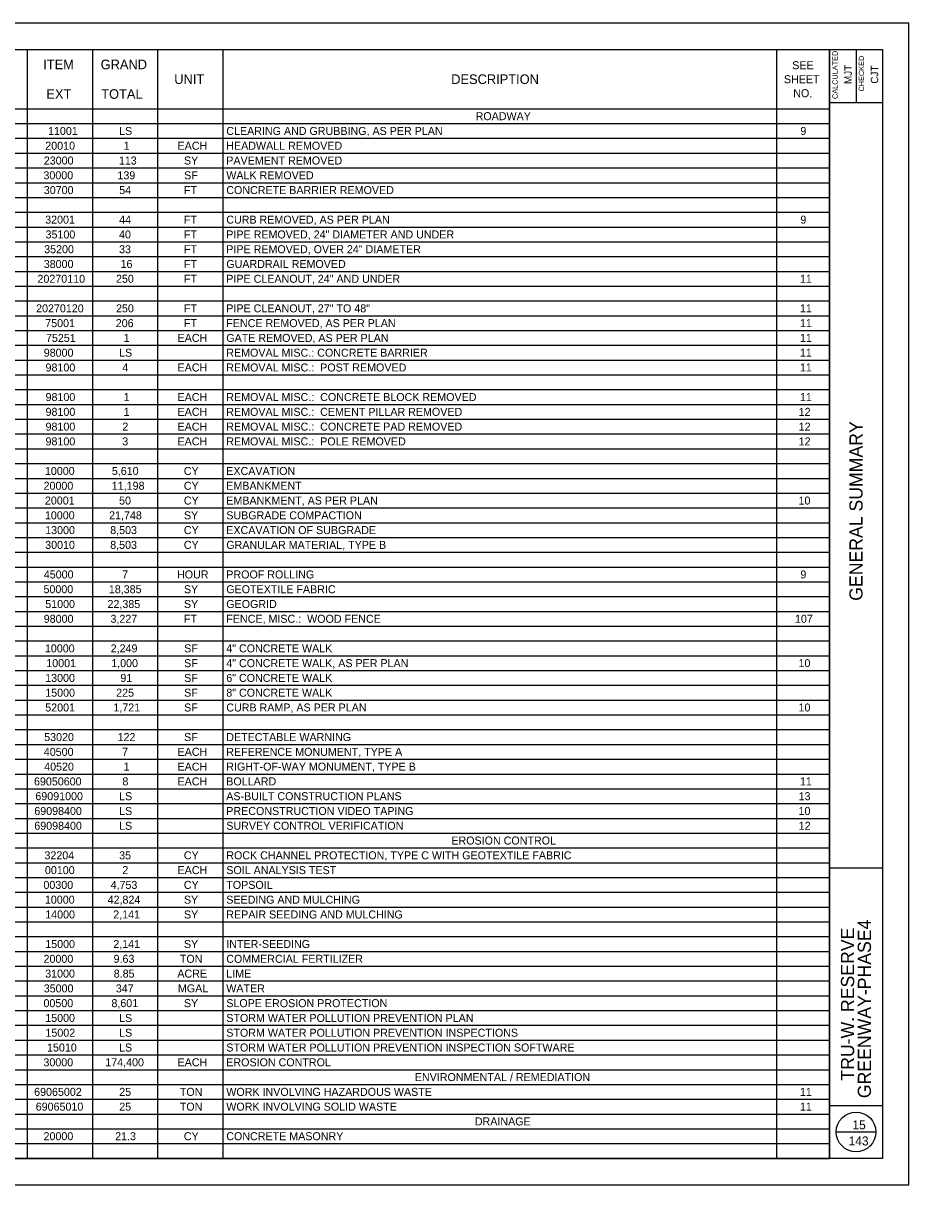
# Model space of a CAD drawing. Extents: x -16 to 102, y -13 to 9.
# Drawn here: x 0.85 to 17.63, y -12.91 to 9.09 of the extents above; entities that cross this region are included whole.
import ezdxf

# ---------------------------------------------------------------- set-up
doc = ezdxf.new("R2010")
doc.units = 0
for name, color, linetype in [('PV_P_EOP', 7, 'Continuous'), ('SH_Border', 7, 'Continuous'), ('SH_Cut_Line', 7, 'Continuous'), ('SH_Data', 7, 'Continuous'), ('TX_P_1', 7, 'Continuous')]:
    doc.layers.add(name, color=color, linetype=linetype)

msp = doc.modelspace()

# ---------------------------------------------------------------- linework, layer by layer
at = {"layer": 'SH_Border'}
for p, q in [((16.129, -12.407), (16.129, 8.593)), ((16.629, 8.593), (16.629, 7.593)), ((16.129, 7.593), (17.129, 7.593)), ((16.129, -6.907), (17.129, -6.907)), ((16.129, -11.407), (17.129, -11.407))]:
    msp.add_line(p, q, dxfattribs=at)
msp.add_lwpolyline([(-14.371, 8.593), (17.129, 8.593), (17.129, -12.407), (-14.371, -12.407)], close=True, dxfattribs=at)
at = {"layer": 'SH_Cut_Line'}
msp.add_lwpolyline([(-16.371, -12.907), (17.629, -12.907), (17.629, 9.093), (-16.371, 9.093)], close=True, dxfattribs=at)
at = {"layer": 'SH_Data'}
msp.add_line((16.254, -11.907), (17.004, -11.907), dxfattribs=at)
msp.add_circle((16.629, -11.907), 0.375, dxfattribs=at)
at = {"layer": 'TX_P_1'}
for p, q in [((-14.371, 8.593), (16.129, 8.593)), ((0.928, 8.593), (0.928, -12.407)), ((2.163, 8.593), (2.163, -12.407)), ((3.398, 8.593), (3.398, -12.407)), ((4.634, 8.593), (4.634, -12.407)), ((15.124, 8.593), (15.124, -12.407)), ((16.129, 8.593), (16.129, -12.407)), ((-14.371, 7.473), (16.129, 7.473)), ((-14.371, 7.193), (16.129, 7.193)), ((-14.371, 6.913), (16.129, 6.913)), ((-14.371, 6.633), (16.129, 6.633)), ((-14.371, 6.353), (16.129, 6.353)), ((-14.371, 6.073), (16.129, 6.073)), ((-14.371, 5.793), (16.129, 5.793)), ((-14.371, 5.513), (16.129, 5.513)), ((-14.371, 5.233), (16.129, 5.233)), ((-14.371, 4.953), (16.129, 4.953)), ((-14.371, 4.673), (16.129, 4.673)), ((-14.371, 4.393), (16.129, 4.393)), ((-14.371, 4.113), (16.129, 4.113)), ((-14.371, 3.833), (16.129, 3.833)), ((-14.371, 3.553), (16.129, 3.553)), ((-14.371, 3.273), (16.129, 3.273)), ((-14.371, 2.993), (16.129, 2.993)), ((-14.371, 2.713), (16.129, 2.713)), ((-14.371, 2.433), (16.129, 2.433)), ((-14.371, 2.153), (16.129, 2.153)), ((-14.371, 1.873), (16.129, 1.873)), ((-14.371, 1.593), (16.129, 1.593)), ((-14.371, 1.313), (16.129, 1.313)), ((-14.371, 1.033), (16.129, 1.033)), ((-14.371, 0.753), (16.129, 0.753)), ((-14.371, 0.473), (16.129, 0.473)), ((-14.371, 0.193), (16.129, 0.193)), ((-14.371, -0.087), (16.129, -0.087)), ((-14.371, -0.367), (16.129, -0.367)), ((-14.371, -0.647), (16.129, -0.647)), ((-14.371, -0.927), (16.129, -0.927)), ((-14.371, -1.207), (16.129, -1.207)), ((-14.371, -1.487), (16.129, -1.487)), ((-14.371, -1.767), (16.129, -1.767)), ((-14.371, -2.047), (16.129, -2.047)), ((-14.371, -2.327), (16.129, -2.327)), ((-14.371, -2.607), (16.129, -2.607)), ((-14.371, -2.887), (16.129, -2.887)), ((-14.371, -3.167), (16.129, -3.167)), ((-14.371, -3.447), (16.129, -3.447)), ((-14.371, -3.727), (16.129, -3.727)), ((-14.371, -4.007), (16.129, -4.007)), ((-14.371, -4.287), (16.129, -4.287)), ((-14.371, -4.567), (16.129, -4.567)), ((-14.371, -4.847), (16.129, -4.847)), ((-14.371, -5.127), (16.129, -5.127)), ((-14.371, -5.407), (16.129, -5.407)), ((-14.371, -5.687), (16.129, -5.687)), ((-14.371, -5.967), (16.129, -5.967)), ((-14.371, -6.247), (16.129, -6.247)), ((-14.371, -6.527), (16.129, -6.527)), ((-14.371, -6.807), (16.129, -6.807)), ((-14.371, -7.087), (16.129, -7.087)), ((-14.371, -7.367), (16.129, -7.367)), ((-14.371, -7.647), (16.129, -7.647)), ((-14.371, -7.927), (16.129, -7.927)), ((-14.371, -8.207), (16.129, -8.207)), ((-14.371, -8.487), (16.129, -8.487)), ((-14.371, -8.767), (16.129, -8.767)), ((-14.371, -9.047), (16.129, -9.047)), ((-14.371, -9.327), (16.129, -9.327)), ((-14.371, -9.607), (16.129, -9.607)), ((-14.371, -9.887), (16.129, -9.887)), ((-14.371, -10.167), (16.129, -10.167)), ((-14.371, -10.447), (16.129, -10.447)), ((-14.371, -10.727), (16.129, -10.727)), ((-14.371, -11.007), (16.129, -11.007)), ((-14.371, -11.287), (16.129, -11.287)), ((-14.371, -11.567), (16.129, -11.567)), ((-14.371, -11.847), (16.129, -11.847)), ((-14.371, -12.127), (16.129, -12.127)), ((-14.371, -12.407), (16.129, -12.407))]:
    msp.add_line(p, q, dxfattribs=at)

# ---------------------------------------------------------------- texts
at = {"layer": 'PV_P_EOP'}
for s, height, p in [('ROADWAY', 0.1515, (9.423, 7.257)), ('EROSION CONTROL', 0.15153, (8.963, -6.463)), ('ENVIRONMENTAL / REMEDIATION', 0.15153, (8.271, -10.943)), ('DRAINAGE', 0.1515, (9.408, -11.783))]:
    msp.add_text(s, height=height, dxfattribs=at).set_placement(p)
at = {"layer": 'SH_Data'}
for s, height, p in [('CALCULATED', 0.1, (16.281, 7.658)), ('CHECKED', 0.1, (16.781, 7.801)), ('MJT', 0.14, (16.549, 7.942)), ('CJT', 0.14, (17.049, 7.949)), ('GENERAL SUMMARY', 0.25, (16.754, -1.846)), ('GREENWAY-PHASE4', 0.25, (16.913, -11.266)), ('TRU-W. RESERVE', 0.25, (16.594, -10.934))]:
    msp.add_text(s, height=height, rotation=90, dxfattribs=at).set_placement(p)
for s, p in [('15', (16.561, -11.857)), ('143', (16.488, -12.162))]:
    msp.add_text(s, height=0.17, dxfattribs=at).set_placement(p)
at = {"layer": 'TX_P_1'}
for s, height, p in [('ITEM', 0.1818, (1.231, 8.222)), ('GRAND', 0.1818, (2.319, 8.222)), ('SEE', 0.1515, (15.421, 8.222)), ('UNIT', 0.1818, (3.714, 7.942)), ('DESCRIPTION', 0.18184, (8.96, 7.942)), ('SHEET', 0.1515, (15.263, 7.957)), ('EXT', 0.1818, (1.291, 7.662)), ('TOTAL', 0.1818, (2.33, 7.662)), ('NO.', 0.1515, (15.44, 7.692)), ('11001', 0.1515, (1.322, 6.977)), ('LS', 0.1515, (2.668, 6.977)), ('CLEARING AND GRUBBING, AS PER PLAN', 0.15153, (4.699, 6.977)), ('9', 0.152, (15.575, 6.977)), ('20010', 0.1515, (1.27, 6.697)), ('1', 0.152, (2.753, 6.697)), ('EACH', 0.1515, (3.776, 6.697)), ('HEADWALL REMOVED', 0.15153, (4.699, 6.697)), ('23000', 0.1515, (1.242, 6.417)), ('113', 0.1515, (2.664, 6.417)), ('SY', 0.1515, (3.897, 6.417)), ('PAVEMENT REMOVED', 0.15153, (4.699, 6.417)), ('30000', 0.1515, (1.235, 6.137)), ('139', 0.1515, (2.637, 6.137)), ('SF', 0.1515, (3.901, 6.137)), ('WALK REMOVED', 0.15153, (4.699, 6.137)), ('30700', 0.1515, (1.242, 5.857)), ('54', 0.1515, (2.671, 5.857)), ('FT', 0.1515, (3.897, 5.857)), ('CONCRETE BARRIER REMOVED', 0.15153, (4.699, 5.857)), ('32001', 0.1515, (1.268, 5.297)), ('44', 0.1515, (2.671, 5.297)), ('FT', 0.1515, (3.897, 5.297)), ('CURB REMOVED, AS PER PLAN', 0.15153, (4.699, 5.297)), ('9', 0.152, (15.575, 5.297)), ('35100', 0.1515, (1.275, 5.017)), ('40', 0.1515, (2.667, 5.017)), ('FT', 0.1515, (3.897, 5.017)), ('PIPE REMOVED, 24" DIAMETER AND UNDER', 0.15153, (4.699, 5.017)), ('35200', 0.1515, (1.249, 4.737)), ('33', 0.1515, (2.668, 4.737)), ('FT', 0.1515, (3.897, 4.737)), ('PIPE REMOVED, OVER 24" DIAMETER', 0.15153, (4.699, 4.737)), ('38000', 0.1515, (1.241, 4.457)), ('16', 0.1515, (2.696, 4.457)), ('FT', 0.1515, (3.897, 4.457)), ('GUARDRAIL REMOVED', 0.15153, (4.699, 4.457)), ('20270110', 0.1515, (1.122, 4.177)), ('250', 0.1515, (2.61, 4.177)), ('FT', 0.1515, (3.897, 4.177)), ('PIPE CLEANOUT, 24" AND UNDER', 0.15153, (4.699, 4.177)), ('11', 0.1515, (15.566, 4.177)), ('20270120', 0.1515, (1.096, 3.617)), ('250', 0.1515, (2.61, 3.617)), ('FT', 0.1515, (3.897, 3.617)), ('PIPE CLEANOUT, 27" TO 48"', 0.15153, (4.699, 3.617)), ('11', 0.1515, (15.566, 3.617)), ('75001', 0.1515, (1.269, 3.337)), ('206', 0.1515, (2.605, 3.337)), ('FT', 0.1515, (3.897, 3.337)), ('FENCE REMOVED, AS PER PLAN', 0.15153, (4.699, 3.337)), ('11', 0.1515, (15.566, 3.337)), ('75251', 0.1515, (1.283, 3.057)), ('1', 0.152, (2.753, 3.057)), ('EACH', 0.1515, (3.776, 3.057)), ('GATE REMOVED, AS PER PLAN', 0.15153, (4.699, 3.057)), ('11', 0.1515, (15.566, 3.057)), ('98000', 0.1515, (1.241, 2.777)), ('LS', 0.1515, (2.668, 2.777)), ('REMOVAL MISC.: CONCRETE BARRIER', 0.15153, (4.699, 2.777)), ('11', 0.1515, (15.566, 2.777)), ('98100', 0.1515, (1.275, 2.497)), ('4', 0.152, (2.73, 2.497)), ('EACH', 0.1515, (3.776, 2.497)), ('REMOVAL MISC.:  POST REMOVED', 0.15153, (4.699, 2.497)), ('11', 0.1515, (15.566, 2.497)), ('98100', 0.1515, (1.275, 1.937)), ('1', 0.152, (2.753, 1.937)), ('EACH', 0.1515, (3.776, 1.937)), ('REMOVAL MISC.:  CONCRETE BLOCK REMOVED', 0.15153, (4.699, 1.937)), ('11', 0.1515, (15.566, 1.937)), ('98100', 0.1515, (1.275, 1.657)), ('1', 0.152, (2.753, 1.657)), ('EACH', 0.1515, (3.776, 1.657)), ('REMOVAL MISC.:  CEMENT PILLAR REMOVED', 0.15153, (4.699, 1.657)), ('12', 0.1515, (15.543, 1.657)), ('98100', 0.1515, (1.275, 1.377)), ('2', 0.152, (2.73, 1.377)), ('EACH', 0.1515, (3.776, 1.377)), ('REMOVAL MISC.:  CONCRETE PAD REMOVED', 0.15153, (4.699, 1.377)), ('12', 0.1515, (15.543, 1.377)), ('98100', 0.1515, (1.275, 1.097)), ('3', 0.152, (2.728, 1.097)), ('EACH', 0.1515, (3.776, 1.097)), ('REMOVAL MISC.:  POLE REMOVED', 0.15153, (4.699, 1.097)), ('12', 0.1515, (15.543, 1.097)), ('10000', 0.1515, (1.263, 0.537)), ('5,610', 0.1515, (2.531, 0.537)), ('CY', 0.1515, (3.895, 0.537)), ('EXCAVATION', 0.1515, (4.699, 0.537)), ('20000', 0.1515, (1.237, 0.257)), ('11,198', 0.1515, (2.53, 0.257)), ('CY', 0.1515, (3.895, 0.257)), ('EMBANKMENT', 0.1515, (4.699, 0.257)), ('20001', 0.1515, (1.263, -0.023)), ('50', 0.1515, (2.668, -0.023)), ('CY', 0.1515, (3.895, -0.023)), ('EMBANKMENT, AS PER PLAN', 0.15153, (4.699, -0.023)), ('10', 0.1515, (15.54, -0.023)), ('10000', 0.1515, (1.263, -0.303)), ('21,748', 0.1515, (2.479, -0.303)), ('SY', 0.1515, (3.897, -0.303)), ('SUBGRADE COMPACTION', 0.15153, (4.699, -0.303)), ('13000', 0.1515, (1.268, -0.583)), ('8,503', 0.1515, (2.5, -0.583)), ('CY', 0.1515, (3.895, -0.583)), ('EXCAVATION OF SUBGRADE', 0.15153, (4.699, -0.583)), ('30010', 0.1515, (1.268, -0.863)), ('8,503', 0.1515, (2.5, -0.863)), ('CY', 0.1515, (3.895, -0.863)), ('GRANULAR MATERIAL, TYPE B', 0.15153, (4.699, -0.863)), ('45000', 0.1515, (1.242, -1.423)), ('7', 0.152, (2.726, -1.423)), ('HOUR', 0.1515, (3.766, -1.423)), ('PROOF ROLLING', 0.15153, (4.699, -1.423)), ('9', 0.152, (15.575, -1.423)), ('50000', 0.1515, (1.236, -1.703)), ('18,385', 0.1515, (2.474, -1.703)), ('SY', 0.1515, (3.897, -1.703)), ('GEOTEXTILE FABRIC', 0.15153, (4.699, -1.703)), ('51000', 0.1515, (1.269, -1.983)), ('22,385', 0.1515, (2.449, -1.983)), ('SY', 0.1515, (3.897, -1.983)), ('GEOGRID', 0.1515, (4.699, -1.983)), ('98000', 0.1515, (1.241, -2.263)), ('3,227', 0.1515, (2.505, -2.263)), ('FT', 0.1515, (3.897, -2.263)), ('FENCE, MISC.:  WOOD FENCE', 0.15153, (4.699, -2.263)), ('107', 0.1515, (15.473, -2.263)), ('10000', 0.1515, (1.263, -2.823)), ('2,249', 0.1515, (2.509, -2.823)), ('SF', 0.1515, (3.901, -2.823)), ('4" CONCRETE WALK', 0.15153, (4.699, -2.823)), ('10001', 0.1515, (1.289, -3.103)), ('1,000', 0.1515, (2.519, -3.103)), ('SF', 0.1515, (3.901, -3.103)), ('4" CONCRETE WALK, AS PER PLAN', 0.15153, (4.699, -3.103)), ('10', 0.1515, (15.54, -3.103)), ('13000', 0.1515, (1.268, -3.383)), ('91', 0.1515, (2.692, -3.383)), ('SF', 0.1515, (3.901, -3.383)), ('6" CONCRETE WALK', 0.15153, (4.699, -3.383)), ('15000', 0.1515, (1.269, -3.663)), ('225', 0.1515, (2.613, -3.663)), ('SF', 0.1515, (3.901, -3.663)), ('8" CONCRETE WALK', 0.15153, (4.699, -3.663)), ('52001', 0.1515, (1.269, -3.943)), ('1,721', 0.1515, (2.56, -3.943)), ('SF', 0.1515, (3.901, -3.943)), ('CURB RAMP, AS PER PLAN', 0.15153, (4.699, -3.943)), ('10', 0.1515, (15.54, -3.943)), ('53020', 0.1515, (1.249, -4.503)), ('122', 0.1515, (2.64, -4.503)), ('SF', 0.1515, (3.901, -4.503)), ('DETECTABLE WARNING', 0.15153, (4.699, -4.503)), ('40500', 0.1515, (1.242, -4.783)), ('7', 0.152, (2.726, -4.783)), ('EACH', 0.1515, (3.776, -4.783)), ('REFERENCE MONUMENT, TYPE A', 0.15153, (4.699, -4.783)), ('40520', 0.1515, (1.249, -5.063)), ('1', 0.152, (2.753, -5.063)), ('EACH', 0.1515, (3.776, -5.063)), ('RIGHT-OF-WAY MONUMENT, TYPE B', 0.15153, (4.699, -5.063)), ('69050600', 0.1515, (1.056, -5.343)), ('8', 0.152, (2.731, -5.343)), ('EACH', 0.1515, (3.776, -5.343)), ('BOLLARD', 0.1515, (4.699, -5.343)), ('11', 0.1515, (15.566, -5.343)), ('69091000', 0.1515, (1.082, -5.623)), ('LS', 0.1515, (2.668, -5.623)), ('AS-BUILT CONSTRUCTION PLANS', 0.15153, (4.699, -5.623)), ('13', 0.1515, (15.542, -5.623)), ('69098400', 0.1515, (1.062, -5.903)), ('LS', 0.1515, (2.668, -5.903)), ('PRECONSTRUCTION VIDEO TAPING', 0.15153, (4.699, -5.903)), ('10', 0.1515, (15.54, -5.903)), ('69098400', 0.1515, (1.062, -6.183)), ('LS', 0.1515, (2.668, -6.183)), ('SURVEY CONTROL VERIFICATION', 0.15153, (4.699, -6.183)), ('12', 0.1515, (15.543, -6.183)), ('32204', 0.1515, (1.254, -6.743)), ('35', 0.1515, (2.669, -6.743)), ('CY', 0.1515, (3.895, -6.743)), ('ROCK CHANNEL PROTECTION, TYPE C WITH GEOTEXTILE FABRIC', 0.15153, (4.699, -6.743)), ('00100', 0.1515, (1.263, -7.023)), ('2', 0.152, (2.73, -7.023)), ('EACH', 0.1515, (3.776, -7.023)), ('SOIL ANALYSIS TEST', 0.15153, (4.699, -7.023)), ('00300', 0.1515, (1.235, -7.303)), ('4,753', 0.1515, (2.507, -7.303)), ('CY', 0.1515, (3.895, -7.303)), ('TOPSOIL', 0.1515, (4.699, -7.303)), ('10000', 0.1515, (1.263, -7.583)), ('42,824', 0.1515, (2.451, -7.583)), ('SY', 0.1515, (3.897, -7.583)), ('SEEDING AND MULCHING', 0.15153, (4.699, -7.583)), ('14000', 0.1515, (1.269, -7.863)), ('2,141', 0.1515, (2.558, -7.863)), ('SY', 0.1515, (3.897, -7.863)), ('REPAIR SEEDING AND MULCHING', 0.15153, (4.699, -7.863)), ('15000', 0.1515, (1.269, -8.423)), ('2,141', 0.1515, (2.558, -8.423)), ('SY', 0.1515, (3.897, -8.423)), ('INTER-SEEDING', 0.15153, (4.699, -8.423)), ('20000', 0.1515, (1.237, -8.703)), ('9.63', 0.1515, (2.564, -8.703)), ('TON', 0.1515, (3.819, -8.703)), ('COMMERCIAL FERTILIZER', 0.15153, (4.699, -8.703)), ('31000', 0.1515, (1.268, -8.983)), ('8.85', 0.1515, (2.567, -8.983)), ('ACRE', 0.1515, (3.772, -8.983)), ('LIME', 0.1515, (4.699, -8.983)), ('35000', 0.1515, (1.241, -9.263)), ('347', 0.1515, (2.606, -9.263)), ('MGAL', 0.1515, (3.783, -9.263)), ('WATER', 0.1515, (4.699, -9.263)), ('00500', 0.1515, (1.236, -9.543)), ('8,601', 0.1515, (2.523, -9.543)), ('SY', 0.1515, (3.897, -9.543)), ('SLOPE EROSION PROTECTION', 0.15153, (4.699, -9.543)), ('15000', 0.1515, (1.269, -9.823)), ('LS', 0.1515, (2.668, -9.823)), ('STORM WATER POLLUTION PREVENTION PLAN', 0.15153, (4.699, -9.823)), ('15002', 0.1515, (1.273, -10.103)), ('LS', 0.1515, (2.668, -10.103)), ('STORM WATER POLLUTION PREVENTION INSPECTIONS', 0.15153, (4.699, -10.103)), ('15010', 0.1515, (1.303, -10.383)), ('LS', 0.1515, (2.668, -10.383)), ('STORM WATER POLLUTION PREVENTION INSPECTION SOFTWARE', 0.15153, (4.699, -10.383)), ('30000', 0.1515, (1.235, -10.663)), ('174,400', 0.1515, (2.407, -10.663)), ('EACH', 0.1515, (3.776, -10.663)), ('EROSION CONTROL', 0.15153, (4.699, -10.663)), ('69065002', 0.1515, (1.059, -11.223)), ('25', 0.1515, (2.671, -11.223)), ('TON', 0.1515, (3.819, -11.223)), ('WORK INVOLVING HAZARDOUS WASTE', 0.15153, (4.699, -11.223)), ('11', 0.1515, (15.566, -11.223)), ('69065010', 0.1515, (1.089, -11.503)), ('25', 0.1515, (2.671, -11.503)), ('TON', 0.1515, (3.819, -11.503)), ('WORK INVOLVING SOLID WASTE', 0.15153, (4.699, -11.503)), ('11', 0.1515, (15.566, -11.503)), ('20000', 0.1515, (1.237, -12.063)), ('21.3', 0.1515, (2.594, -12.063)), ('CY', 0.1515, (3.895, -12.063)), ('CONCRETE MASONRY', 0.15153, (4.699, -12.063))]:
    msp.add_text(s, height=height, dxfattribs=at).set_placement(p)

doc.saveas('drawing.dxf')
